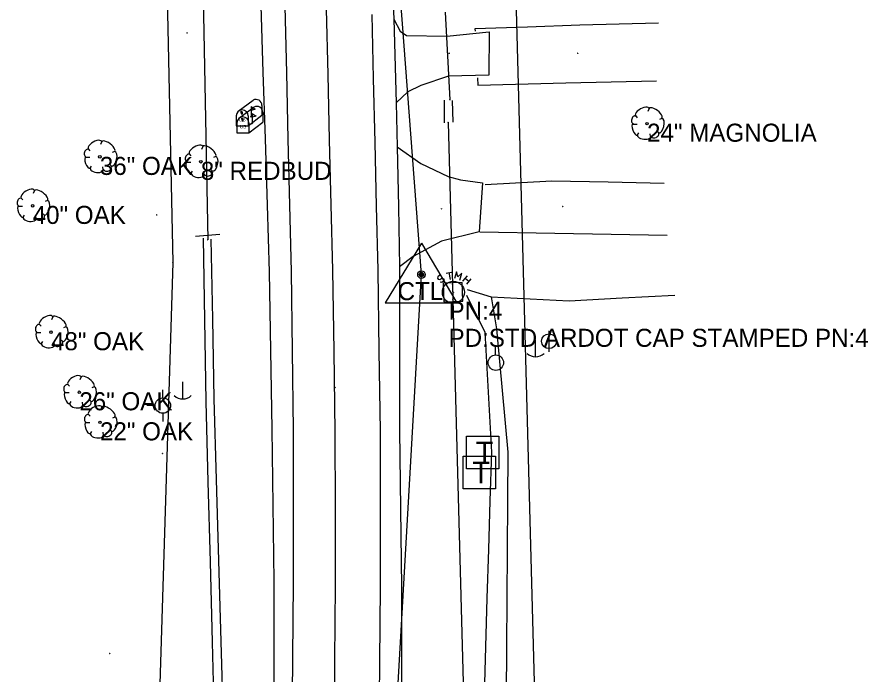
# Model space of a CAD drawing. Extents: x 1930288 to 1941089, y 588389 to 611475.
# Drawn here: x 1930834.2 to 1931069.7, y 598909.6 to 599091.7 of the extents above; entities that cross this region are included whole.
import ezdxf

# ---------------------------------------------------------------- set-up
doc = ezdxf.new("R2010")
doc.units = 0
for name, color, linetype in [('S_BASELINE', 7, 'Continuous'), ('S_DITCHLINE', 7, 'Continuous'), ('S_DRG_PT_SYM', 7, 'Continuous'), ('S_DRIVEWAY', 7, 'Continuous'), ('S_DROP_INLET', 7, 'Continuous'), ('S_EDGE_CONCRETE', 7, 'Continuous'), ('S_EDGE_PAVEMENT', 7, 'Continuous'), ('S_HEADWALL', 7, 'Continuous'), ('S_MAILBOX', 7, 'Continuous'), ('S_MSC_PT_SYM', 7, 'Continuous'), ('S_PAVEMENT_CROWN', 7, 'Continuous'), ('S_PRIMARY_CTL', 7, 'Continuous'), ('S_PRIMARY_CTL_ANNOT', 7, 'Continuous'), ('S_SANITARY_SEWER', 7, 'Continuous'), ('S_SHOULDER', 7, 'Continuous'), ('S_SIDE_DRAIN', 7, 'Continuous'), ('S_STORM_SEWER', 7, 'Continuous'), ('S_TELEPHONE_UTILITIES', 7, 'Continuous'), ('S_TREE', 7, 'Continuous'), ('S_TREE_ANNOT', 7, 'Continuous'), ('S_UTILITY_POLE', 7, 'Continuous'), ('S_UTL_PT_SYM', 7, 'Continuous'), ('S_WATER_UTILITIES', 7, 'Continuous')]:
    doc.layers.add(name, color=color, linetype=linetype)

msp = doc.modelspace()

# ---------------------------------------------------------------- linework, layer by layer
at = {"layer": 'S_BASELINE'}
for p, q in [((1930946.09, 599020.44), (1930874, 599969.55)), ((1930894.27, 598110.49), (1930946.09, 599020.44))]:
    msp.add_line(p, q, dxfattribs=at)
at = {"layer": 'S_DITCHLINE'}
for points in [[(1930952.44, 599062.45), (1930952.47, 599068.73)], [(1930954.64, 599068.65), (1930954.8, 599062.64)], [(1930885.69, 599030.55), (1930886.05, 599007.92), (1930886.41, 598985.29), (1930886.99, 598963.11), (1930887.58, 598940.93), (1930888.17, 598918.74), (1930888.75, 598896.56), (1930889.17, 598875.3), (1930889.58, 598854.04), (1930889.99, 598832.79), (1930890.41, 598811.53)], [(1930887.77, 599030.24), (1930888.22, 599008.14), (1930888.67, 598986.05), (1930889.3, 598963.68), (1930889.92, 598941.3), (1930890.55, 598918.93), (1930891.18, 598896.56), (1930891.61, 598875.21), (1930892.04, 598853.86), (1930892.46, 598832.51), (1930892.89, 598811.16)], [(1930958.74, 599016.33), (1930965.42, 599014.25), (1930966.89, 599005.44), (1930968.46, 598988.34), (1930970.03, 598971.25), (1930969.93, 598957.75), (1930969.84, 598944.26), (1930969.75, 598930.76), (1930969.66, 598917.27), (1930969.57, 598903.78), (1930969.47, 598890.28), (1930969.38, 598876.79), (1930969.29, 598863.29), (1930969.48, 598845.28), (1930969.68, 598827.26), (1930969.99, 598803.42), (1930970.29, 598779.58), (1930970.6, 598755.74), (1930970.91, 598731.9), (1930970.72, 598716.01)], [(1930958.59, 599014.73), (1930963.59, 599004.53), (1930964.52, 598987.9), (1930965.44, 598971.28), (1930965.04, 598957.82), (1930964.63, 598944.36), (1930964.22, 598930.9), (1930963.81, 598917.44), (1930963.41, 598903.98), (1930963, 598890.52), (1930962.59, 598877.06), (1930962.18, 598863.6), (1930964.65, 598848.03), (1930967.12, 598832.47), (1930964.95, 598829.79), (1930963.99, 598828.88), (1930965.68, 598827.27), (1930964.71, 598803.83), (1930963.74, 598780.39), (1930962.77, 598756.95), (1930961.8, 598733.51), (1930961.71, 598717.5)], [(1930965.42, 599014.25), (1930987.01, 599013.18), (1931001.64, 599013.96), (1931016.26, 599014.74)]]:
    msp.add_lwpolyline(points, dxfattribs=at)
at = {"layer": 'S_DRG_PT_SYM'}
for points in [[(1930953.96, 599068.83), (1930953.96, 599068.88), (1930953.96, 599068.83), (1930953.91, 599068.83), (1930953.96, 599068.83), (1930953.96, 599068.78), (1930953.96, 599068.83), (1930954.01, 599068.83)], [(1930886.94, 599030.09), (1930886.94, 599030.14), (1930886.94, 599030.09), (1930886.89, 599030.09), (1930886.94, 599030.09), (1930886.94, 599030.04), (1930886.94, 599030.09), (1930886.99, 599030.09)]]:
    msp.add_lwpolyline(points, dxfattribs=at)
at = {"layer": 'S_DRIVEWAY'}
for points in [[(1930938.49, 599091.15), (1930940.2, 599087.82), (1930941.97, 599086.65), (1930953.14, 599086.46), (1930964.87, 599087.64), (1930964.77, 599075.64), (1930953.55, 599075.4), (1930945.96, 599072.75), (1930942.29, 599070.99), (1930939.12, 599068.01)], [(1930939.38, 599055.8), (1930945.92, 599051.16), (1930953.51, 599047.61), (1930956.87, 599046.62), (1930962.96, 599045.81), (1930962.04, 599032.24), (1930951.65, 599029.71), (1930943.81, 599025.42), (1930940.06, 599022.62)], [(1931013.31, 599045.69), (1930997.77, 599046.01), (1930982.22, 599046.32), (1930963.69, 599045.24)], [(1930962.23, 599032.28), (1930983.04, 599031.91), (1930998.56, 599031.63), (1931014.09, 599031.35)]]:
    msp.add_lwpolyline(points, dxfattribs=at)
at = {"layer": 'S_DROP_INLET'}
for points in [[(1930957.34, 599018.23), (1930952.11, 599018.06)], [(1930952.11, 599018.06), (1930952.33, 599012.94), (1930957.55, 599013.08), (1930957.34, 599018.23)]]:
    msp.add_lwpolyline(points, dxfattribs=at)
at = {"layer": 'S_EDGE_CONCRETE'}
for points in [[(1931011.7, 599090.04), (1930989.92, 599089.47), (1930975.42, 599088.96), (1930960.91, 599088.45), (1930960.95, 599087.77)], [(1930961.57, 599074.91), (1930961.69, 599072.87), (1930986.04, 599073.53), (1930998.6, 599073.77), (1931011.15, 599074.02)]]:
    msp.add_lwpolyline(points, dxfattribs=at)
at = {"layer": 'S_EDGE_PAVEMENT'}
for points in [[(1930908.24, 599094.62), (1930908.7, 599076.29), (1930909.15, 599057.96), (1930909.61, 599039.62), (1930910.07, 599021.29), (1930910.34, 598999.36), (1930910.62, 598977.42), (1930910.62, 598956.27), (1930910.61, 598935.13), (1930910.4, 598914.36), (1930910.19, 598893.6), (1930909.84, 598873.38), (1930909.49, 598853.17), (1930908.82, 598831.47), (1930908.16, 598809.77), (1930907.16, 598787.82), (1930906.16, 598765.87), (1930904.92, 598744.7), (1930903.67, 598723.53)], [(1930932.32, 599092.44), (1930932.75, 599074.74), (1930933.17, 599057.04), (1930933.6, 599039.34), (1930934.02, 599021.64), (1930934.34, 598999.38), (1930934.66, 598977.12), (1930934.67, 598955.54), (1930934.68, 598933.95), (1930934.5, 598913.33), (1930934.31, 598892.71), (1930933.93, 598872.55), (1930933.55, 598852.4), (1930932.9, 598830.68), (1930932.25, 598808.95), (1930931.34, 598786.48), (1930930.43, 598764), (1930929.16, 598742.91), (1930927.89, 598721.82)]]:
    msp.add_lwpolyline(points, dxfattribs=at)
at = {"layer": 'S_HEADWALL'}
msp.add_lwpolyline([(1930883.57, 599031.03), (1930890.32, 599031.61)], dxfattribs=at)
at = {"layer": 'S_MAILBOX'}
for p, q in [((1930895.38, 599065.63), (1930899.52, 599068.74)), ((1930895.59, 599063.7), (1930899.73, 599066.81)), ((1930899, 599066.92), (1930899, 599064.2)), ((1930901.95, 599067.26), (1930901.95, 599064.55)), ((1930902.16, 599065.34), (1930902.16, 599062.62)), ((1930894.83, 599064.35), (1930894.83, 599061.64)), ((1930898.15, 599061.64), (1930901.95, 599064.55)), ((1930898.15, 599064.35), (1930898.15, 599061.64)), ((1930899.21, 599064.99), (1930899.21, 599062.28)), ((1930894.83, 599061.64), (1930898.15, 599061.64)), ((1930895.04, 599062.43), (1930895.04, 599059.71)), ((1930898.36, 599059.71), (1930902.16, 599062.62)), ((1930898.36, 599062.43), (1930898.36, 599059.71)), ((1930895.04, 599059.71), (1930898.36, 599059.71))]:
    msp.add_line(p, q, dxfattribs=at)
for points in [[(1930896.01, 599065.47), (1930896.24, 599065.33), (1930896.24, 599064.94), (1930896.54, 599064.94), (1930896.54, 599065.3), (1930896.35, 599065.55), (1930896.01, 599065.5)], [(1930899, 599066.92), (1930900.11, 599066.25), (1930899, 599065.9)], [(1930896.22, 599063.54), (1930896.45, 599063.41), (1930896.45, 599063.02), (1930896.75, 599063.02), (1930896.75, 599063.38), (1930896.56, 599063.63), (1930896.22, 599063.57)], [(1930899.21, 599064.99), (1930900.32, 599064.33), (1930899.21, 599063.98)]]:
    msp.add_lwpolyline(points, dxfattribs=at)
for centre, end in [((1930900.29, 599067.26), 117.5718), ((1930896.49, 599064.35), 180), ((1930900.5, 599065.34), 117.5718), ((1930896.7, 599062.43), 180)]:
    msp.add_arc(centre, 1.66, 0, end, dxfattribs=at)
for centre in [(1930899, 599064.2), (1930899.21, 599062.28)]:
    msp.add_ellipse(centre, major_axis=(0.145, 0.132), ratio=0.564646, dxfattribs=at)
at = {"layer": 'S_MSC_PT_SYM'}
for points in [[(1930953.79, 599081.72), (1930953.79, 599081.77), (1930953.79, 599081.72), (1930953.74, 599081.72), (1930953.79, 599081.72), (1930953.79, 599081.67), (1930953.79, 599081.72), (1930953.84, 599081.72)], [(1930989.36, 599081.71), (1930989.36, 599081.76), (1930989.36, 599081.71), (1930989.31, 599081.71), (1930989.36, 599081.71), (1930989.36, 599081.66), (1930989.36, 599081.71), (1930989.41, 599081.71)], [(1930985.2, 599039.25), (1930985.2, 599039.3), (1930985.2, 599039.25), (1930985.15, 599039.25), (1930985.2, 599039.25), (1930985.2, 599039.2), (1930985.2, 599039.25), (1930985.25, 599039.25)], [(1930951.67, 599038.65), (1930951.67, 599038.7), (1930951.67, 599038.65), (1930951.62, 599038.65), (1930951.67, 599038.65), (1930951.67, 599038.6), (1930951.67, 599038.65), (1930951.72, 599038.65)], [(1930954.68, 599017.62), (1930954.68, 599017.67), (1930954.68, 599017.62), (1930954.63, 599017.62), (1930954.68, 599017.62), (1930954.68, 599017.57), (1930954.68, 599017.62), (1930954.73, 599017.62)], [(1930954.8, 599013.58), (1930954.8, 599013.64), (1930954.8, 599013.58), (1930954.75, 599013.58), (1930954.8, 599013.58), (1930954.8, 599013.53), (1930954.8, 599013.58), (1930954.85, 599013.58)], [(1930922.2, 598989.2), (1930922.2, 598989.25), (1930922.2, 598989.2), (1930922.15, 598989.2), (1930922.2, 598989.2), (1930922.2, 598989.15), (1930922.2, 598989.2), (1930922.25, 598989.2)], [(1930859.83, 598915.58), (1930859.83, 598915.63), (1930859.83, 598915.58), (1930859.78, 598915.58), (1930859.83, 598915.58), (1930859.83, 598915.53), (1930859.83, 598915.58), (1930859.88, 598915.58)]]:
    msp.add_lwpolyline(points, dxfattribs=at)
at = {"layer": 'S_PAVEMENT_CROWN'}
msp.add_lwpolyline([(1930919.68, 599093.9), (1930920.14, 599075.83), (1930920.59, 599057.77), (1930921.04, 599039.71), (1930921.49, 599021.64), (1930921.81, 598999.22), (1930922.13, 598976.81), (1930922.17, 598955.6), (1930922.2, 598934.39), (1930922.05, 598913.69), (1930921.9, 598892.99), (1930921.54, 598872.9), (1930921.18, 598852.8), (1930920.54, 598830.95), (1930919.9, 598809.1), (1930919.28, 598787.14), (1930918.67, 598765.18), (1930917.3, 598743.97), (1930915.93, 598722.77)], dxfattribs=at)
at = {"layer": 'S_PRIMARY_CTL'}
for p, q in [((1930946.09, 599029.14), (1930936.05, 599012.62)), ((1930946.09, 599029.14), (1930955.91, 599012.62)), ((1930936.05, 599012.62), (1930955.91, 599012.62))]:
    msp.add_line(p, q, dxfattribs=at)
for radius in [1.04, 0.609, 0.344]:
    msp.add_circle((1930946.09, 599020.44), radius, dxfattribs=at)
at = {"layer": 'S_SANITARY_SEWER'}
msp.add_line((1930979.26, 598838.38), (1930967.81, 599265.02), dxfattribs=at)
at = {"layer": 'S_SHOULDER'}
for points in [[(1930937.38, 599115.75), (1930938.49, 599091.15), (1930939.12, 599068.01), (1930939.38, 599055.8), (1930939.72, 599039.21), (1930940.06, 599022.62), (1930940.02, 598999.95), (1930939.99, 598977.27), (1930940.29, 598955.61), (1930940.58, 598933.95), (1930940.54, 598913.5), (1930940.49, 598893.05), (1930940.2, 598872.63), (1930939.9, 598852.22), (1930939.23, 598830.34), (1930938.55, 598808.45), (1930937.5, 598786.02), (1930936.44, 598763.59), (1930935.25, 598742.5), (1930934.05, 598721.41)], [(1930901.66, 599094.84), (1930902.24, 599076.43), (1930902.81, 599058.02), (1930903.38, 599039.62), (1930903.95, 599021.21), (1930904.32, 598999.45), (1930904.69, 598977.7), (1930904.98, 598956.64), (1930905.27, 598935.59), (1930905.24, 598914.82), (1930905.22, 598894.05), (1930905.16, 598873.77), (1930905.09, 598853.48), (1930904.3, 598831.27), (1930903.51, 598809.06), (1930901.82, 598785.75), (1930901.57, 598766.31), (1930899.62, 598745.09), (1930897.67, 598723.87)]]:
    msp.add_lwpolyline(points, dxfattribs=at)
at = {"layer": 'S_SIDE_DRAIN'}
for p, q in [((1930884.4, 599167.97), (1930886.94, 599030.09)), ((1930952.67, 599093.04), (1930953.96, 599068.83))]:
    msp.add_line(p, q, dxfattribs=at)
at = {"layer": 'S_STORM_SEWER'}
for p, q in [((1930953.46, 599062.54), (1930954.68, 599017.62)), ((1930952.89, 599020.83), (1930954.4, 599021.1)), ((1930953.66, 599020.98), (1930954.01, 599019.04)), ((1930950.6, 599019.86), (1930950.52, 599019.47)), ((1930950.52, 599019.47), (1930950.72, 599019.2)), ((1930951.14, 599020.24), (1930950.6, 599019.86)), ((1930950.72, 599019.2), (1930951.14, 599019.08)), ((1930951.57, 599020.17), (1930951.14, 599020.24)), ((1930951.14, 599019.08), (1930951.69, 599019.43)), ((1930951.69, 599018.27), (1930951.3, 599018.35)), ((1930951.69, 599019.43), (1930952.15, 599019.35)), ((1930952.23, 599018.66), (1930951.69, 599018.27)), ((1930952.15, 599019.35), (1930952.31, 599019.08)), ((1930952.31, 599019.08), (1930952.23, 599018.66)), ((1930957.58, 599018.62), (1930958.82, 599020.09)), ((1930958.24, 599019.39), (1930959.2, 599018.58)), ((1930959.79, 599019.28), (1930958.55, 599017.8)), ((1930954.68, 599017.62), (1930954.8, 599013.58)), ((1930954.8, 599013.58), (1930959.75, 598830.72))]:
    msp.add_line(p, q, dxfattribs=at)
msp.add_lwpolyline([(1930956.69, 599018.93), (1930957.23, 599020.79), (1930956.18, 599019.78), (1930955.79, 599021.21), (1930955.25, 599019.35)], dxfattribs=at)
msp.add_circle((1930954.93, 599015.55), 3.05, dxfattribs=at)
at = {"layer": 'S_TELEPHONE_UTILITIES'}
for points in [[(1930958.54, 598966.68), (1930958.54, 598975.68), (1930967.54, 598975.68), (1930967.54, 598966.68)], [(1930957.6, 598961.14), (1930957.6, 598970.14), (1930966.6, 598970.14), (1930966.6, 598961.14)]]:
    msp.add_lwpolyline(points, close=True, dxfattribs=at)
at = {"layer": 'S_TREE'}
for p, q in [((1931009.09, 599066.45), (1931008.7, 599065.6)), ((1931005.29, 599064.44), (1931005.79, 599063.86)), ((1931012.65, 599063.66), (1931011.99, 599063.39)), ((1931004.63, 599062.11), (1931005.75, 599062.11)), ((1931005.79, 599058.93), (1931006.26, 599059.63)), ((1931009.47, 599058.66), (1931009.4, 599059.44)), ((1931011.88, 599059.55), (1931011.41, 599059.98)), ((1930857.64, 599057.26), (1930857.25, 599056.41)), ((1930885.59, 599055.9), (1930885.2, 599055.05)), ((1930853.84, 599055.25), (1930854.34, 599054.67)), ((1930861.2, 599054.47), (1930860.54, 599054.2)), ((1930881.79, 599053.89), (1930882.3, 599053.31)), ((1930853.18, 599052.92), (1930854.31, 599052.92)), ((1930881.13, 599051.56), (1930882.26, 599051.56)), ((1930889.15, 599053.11), (1930888.5, 599052.84)), ((1930854.34, 599049.75), (1930854.81, 599050.44)), ((1930858.03, 599049.47), (1930857.95, 599050.25)), ((1930860.43, 599050.37), (1930859.96, 599050.79)), ((1930882.3, 599048.38), (1930882.76, 599049.08)), ((1930885.98, 599048.11), (1930885.9, 599048.89)), ((1930888.38, 599049), (1930887.91, 599049.43)), ((1930835.25, 599041.69), (1930835.75, 599041.11)), ((1930839.04, 599043.71), (1930838.66, 599042.86)), ((1930834.59, 599039.37), (1930835.71, 599039.37)), ((1930842.61, 599040.92), (1930841.95, 599040.65)), ((1930841.83, 599036.81), (1930841.37, 599037.24)), ((1930835.75, 599036.19), (1930836.22, 599036.89)), ((1930839.43, 599035.92), (1930839.35, 599036.7)), ((1930844.12, 599008.74), (1930843.73, 599007.89)), ((1930840.32, 599006.73), (1930840.83, 599006.15)), ((1930839.67, 599004.4), (1930840.79, 599004.4)), ((1930847.69, 599005.95), (1930847.03, 599005.68)), ((1930840.83, 599001.23), (1930841.29, 599001.92)), ((1930844.51, 599000.95), (1930844.43, 599001.73)), ((1930846.91, 599001.85), (1930846.45, 599002.27)), ((1930848.16, 598990.11), (1930848.66, 598989.53)), ((1930851.95, 598992.12), (1930851.57, 598991.27)), ((1930847.5, 598987.78), (1930848.62, 598987.78)), ((1930855.52, 598989.33), (1930854.86, 598989.06)), ((1930848.66, 598984.6), (1930849.12, 598985.3)), ((1930852.34, 598984.33), (1930852.26, 598985.11)), ((1930854.74, 598985.22), (1930854.28, 598985.65)), ((1930857.68, 598983.8), (1930857.29, 598982.95)), ((1930853.88, 598981.79), (1930854.38, 598981.21)), ((1930861.24, 598981.01), (1930860.58, 598980.74)), ((1930853.22, 598979.46), (1930854.35, 598979.46)), ((1930854.38, 598976.29), (1930854.85, 598976.98)), ((1930858.07, 598976.01), (1930857.99, 598976.79)), ((1930860.47, 598976.91), (1930860, 598977.33))]:
    msp.add_line(p, q, dxfattribs=at)
for centre in [(1931008.53, 599062.21), (1930857.08, 599053.02), (1930885.03, 599051.66), (1930838.49, 599039.46), (1930843.56, 599004.5), (1930851.4, 598987.88), (1930857.12, 598979.56)]:
    msp.add_circle(centre, 0.341, dxfattribs=at)
for centre, major_axis, ratio, start_param, end_param in [((1931007.19, 599065.41), (1.86, 1.08), 0.471018, 0, 3.141593), ((1931010.85, 599065.09), (-1.81, 1.36), 0.405113, 3.141593, 6.283186), ((1931004.96, 599063.29), (0.31, 1.03), 0.646762, 0, 3.141593), ((1931012.2, 599061.68), (0.46, 2.04), 0.482994, 3.141593, 6.283185), ((1931005.26, 599060.64), (-0.61, 1.6), 0.420543, 6.283185, 9.424777), ((1931007.72, 599058.86), (-1.83, 0.19), 0.529943, 0, 3.141593), ((1931010.68, 599059.16), (1.09, 0.46), 0.711534, 3.141592, 6.283185), ((1930855.74, 599056.22), (1.86, 1.08), 0.471018, 0, 3.141593), ((1930859.4, 599055.9), (-1.81, 1.36), 0.405113, 3.141593, 6.283186), ((1930883.69, 599054.86), (1.86, 1.08), 0.471018, 0, 3.141593), ((1930887.35, 599054.53), (-1.81, 1.36), 0.405113, 3.141593, 6.283186), ((1930853.51, 599054.11), (0.31, 1.03), 0.646762, 0, 3.141593), ((1930860.75, 599052.49), (0.46, 2.04), 0.482994, 3.141593, 6.283185), ((1930881.46, 599052.74), (0.31, 1.03), 0.646762, 0, 3.141593), ((1930853.81, 599051.46), (-0.61, 1.6), 0.420543, 6.283185, 9.424777), ((1930881.77, 599050.09), (-0.61, 1.6), 0.420543, 6.283185, 9.424777), ((1930888.7, 599051.13), (0.46, 2.04), 0.482994, 3.141593, 6.283185), ((1930856.27, 599049.67), (-1.83, 0.19), 0.529943, 0, 3.141593), ((1930859.23, 599049.97), (1.09, 0.46), 0.711534, 3.141592, 6.283185), ((1930887.18, 599048.61), (1.09, 0.46), 0.711534, 3.141592, 6.283185), ((1930884.23, 599048.31), (-1.83, 0.19), 0.529943, 0, 3.141593), ((1930837.15, 599042.67), (1.86, 1.08), 0.471018, 0, 3.141593), ((1930840.81, 599042.34), (-1.81, 1.36), 0.405113, 3.141593, 6.283186), ((1930834.92, 599040.55), (0.31, 1.03), 0.646762, 0, 3.141593), ((1930835.22, 599037.9), (-0.61, 1.6), 0.420543, 6.283185, 9.424777), ((1930842.16, 599038.93), (0.46, 2.04), 0.482994, 3.141593, 6.283185), ((1930837.68, 599036.12), (-1.83, 0.19), 0.529943, 0, 3.141593), ((1930840.64, 599036.41), (1.09, 0.46), 0.711534, 3.141592, 6.283185), ((1930842.23, 599007.7), (1.86, 1.08), 0.471018, 0, 3.141593), ((1930845.88, 599007.38), (-1.81, 1.36), 0.405113, 3.141593, 6.283186), ((1930839.99, 599005.59), (0.31, 1.03), 0.646762, 0, 3.141593), ((1930840.3, 599002.93), (-0.61, 1.6), 0.420543, 6.283185, 9.424777), ((1930847.24, 599003.97), (0.46, 2.04), 0.482994, 3.141593, 6.283185), ((1930845.72, 599001.45), (1.09, 0.46), 0.711534, 3.141592, 6.283185), ((1930842.76, 599001.15), (-1.83, 0.19), 0.529943, 0, 3.141593), ((1930850.06, 598991.08), (1.86, 1.08), 0.471018, 0, 3.141593), ((1930853.71, 598990.76), (-1.81, 1.36), 0.405113, 3.141593, 6.283186), ((1930847.82, 598988.96), (0.31, 1.03), 0.646762, 0, 3.141593), ((1930848.13, 598986.31), (-0.61, 1.6), 0.420543, 6.283185, 9.424777), ((1930855.07, 598987.35), (0.46, 2.04), 0.482994, 3.141593, 6.283185), ((1930853.55, 598984.83), (1.09, 0.46), 0.711534, 3.141592, 6.283185), ((1930850.59, 598984.53), (-1.83, 0.19), 0.529943, 0, 3.141593), ((1930855.78, 598982.76), (1.86, 1.08), 0.471018, 0, 3.141593), ((1930859.44, 598982.44), (-1.81, 1.36), 0.405113, 3.141593, 6.283186), ((1930853.55, 598980.64), (0.31, 1.03), 0.646762, 0, 3.141593), ((1930860.79, 598979.03), (0.46, 2.04), 0.482994, 3.141593, 6.283185), ((1930853.85, 598977.99), (-0.61, 1.6), 0.420543, 6.283185, 9.424777), ((1930856.31, 598976.21), (-1.83, 0.19), 0.529943, 0, 3.141593), ((1930859.27, 598976.51), (1.09, 0.46), 0.711534, 3.141592, 6.283185)]:
    msp.add_ellipse(centre, major_axis=major_axis, ratio=ratio, start_param=start_param, end_param=end_param, dxfattribs=at)
at = {"layer": 'S_UTILITY_POLE'}
for p, q in [((1930981.41, 598999.07), (1930981.41, 599004.86)), ((1930977.61, 599002.39), (1930977.61, 598997.66)), ((1930966.55, 598998.2), (1930966.55, 599000.31)), ((1930879.98, 598990.72), (1930879.98, 598985.99)), ((1930874.52, 598986.29), (1930874.52, 598988.54)), ((1930872.43, 598984.16), (1930870.1, 598984.16)), ((1930874.6, 598979.74), (1930874.6, 598982.07))]:
    msp.add_line(p, q, dxfattribs=at)
for centre, radius in [((1930981.41, 599002), 2.05), ((1930966.67, 598996.06), 2.13), ((1930874.52, 598984.18), 2.13)]:
    msp.add_circle(centre, radius, dxfattribs=at)
for centre in [(1930977.67, 599001.09), (1930880.04, 598989.42)]:
    msp.add_arc(centre, 3.41, 226.3972, 313.6028, dxfattribs=at)
at = {"layer": 'S_UTL_PT_SYM'}
for points in [[(1930881.23, 599087.32), (1930881.23, 599087.37), (1930881.23, 599087.32), (1930881.18, 599087.32), (1930881.23, 599087.32), (1930881.23, 599087.27), (1930881.23, 599087.32), (1930881.28, 599087.32)], [(1930953.46, 599062.54), (1930953.46, 599062.59), (1930953.46, 599062.54), (1930953.41, 599062.54), (1930953.46, 599062.54), (1930953.46, 599062.49), (1930953.46, 599062.54), (1930953.51, 599062.54)], [(1930872.84, 599036.97), (1930872.84, 599037.02), (1930872.84, 599036.97), (1930872.79, 599036.97), (1930872.84, 599036.97), (1930872.84, 599036.92), (1930872.84, 599036.97), (1930872.89, 599036.97)], [(1930877.25, 599023.82), (1930877.25, 599023.87), (1930877.25, 599023.82), (1930877.2, 599023.82), (1930877.25, 599023.82), (1930877.25, 599023.77), (1930877.25, 599023.82), (1930877.3, 599023.82)], [(1930954.68, 599017.62), (1930954.68, 599017.67), (1930954.68, 599017.62), (1930954.63, 599017.62), (1930954.68, 599017.62), (1930954.68, 599017.57), (1930954.68, 599017.62), (1930954.73, 599017.62)], [(1930954.8, 599013.58), (1930954.8, 599013.64), (1930954.8, 599013.58), (1930954.75, 599013.58), (1930954.8, 599013.58), (1930954.8, 599013.53), (1930954.8, 599013.58), (1930954.85, 599013.58)], [(1930954.93, 599015.55), (1930954.93, 599015.6), (1930954.93, 599015.55), (1930954.88, 599015.55), (1930954.93, 599015.55), (1930954.93, 599015.5), (1930954.93, 599015.55), (1930954.98, 599015.55)], [(1930922.2, 598989.2), (1930922.2, 598989.25), (1930922.2, 598989.2), (1930922.15, 598989.2), (1930922.2, 598989.2), (1930922.2, 598989.15), (1930922.2, 598989.2), (1930922.25, 598989.2)], [(1930874.4, 598970.96), (1930874.4, 598971.01), (1930874.4, 598970.96), (1930874.35, 598970.96), (1930874.4, 598970.96), (1930874.4, 598970.91), (1930874.4, 598970.96), (1930874.45, 598970.96)]]:
    msp.add_lwpolyline(points, dxfattribs=at)
at = {"layer": 'S_WATER_UTILITIES'}
for p, q in [((1930874.23, 599170.75), (1930877.25, 599023.82)), ((1930877.25, 599023.82), (1930871.67, 598842.11))]:
    msp.add_line(p, q, dxfattribs=at)

# ---------------------------------------------------------------- texts
at = {"layer": 'S_MAILBOX'}
for p in [(1930895.59, 599062.83), (1930895.8, 599060.91)]:
    msp.add_text('US', height=0.96, rotation=360, dxfattribs=at).set_placement(p)
at = {"layer": 'S_PRIMARY_CTL'}
msp.add_text('CTL', height=5, rotation=360, dxfattribs=at).set_placement((1930939.5, 599013.36))
at = {"layer": 'S_PRIMARY_CTL_ANNOT'}
for s, p in [('PN:4', (1930953.59, 599007.94)), ('PD:STD ARDOT CAP STAMPED PN:4', (1930953.59, 599000.44))]:
    msp.add_text(s, height=5, dxfattribs=at).set_placement(p)
at = {"layer": 'S_TELEPHONE_UTILITIES'}
for p in [(1930961.11, 598968.18), (1930960.16, 598962.64)]:
    msp.add_text('T', height=6, rotation=360, dxfattribs=at).set_placement(p)
at = {"layer": 'S_TREE_ANNOT'}
for s, p in [('24" MAGNOLIA', (1931008.53, 599057.21)), ('36" OAK', (1930857.08, 599048.02)), ('8" REDBUD', (1930885.03, 599046.66)), ('40" OAK', (1930838.49, 599034.46)), ('48" OAK', (1930843.56, 598999.5)), ('26" OAK', (1930851.4, 598982.88)), ('22" OAK', (1930857.12, 598974.56))]:
    msp.add_text(s, height=5, dxfattribs=at).set_placement(p)

doc.saveas('drawing.dxf')
